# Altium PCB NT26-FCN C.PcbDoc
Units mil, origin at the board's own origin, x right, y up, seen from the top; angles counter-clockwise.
Board outline 1222.67 x 1229.6 mil, 4 copper layers (Top Layer, GND1, Signal Layer 1, Bottom Layer), stack 29.559 mil thick; 1 components, 0 nets, 46 pads, 0 vias.
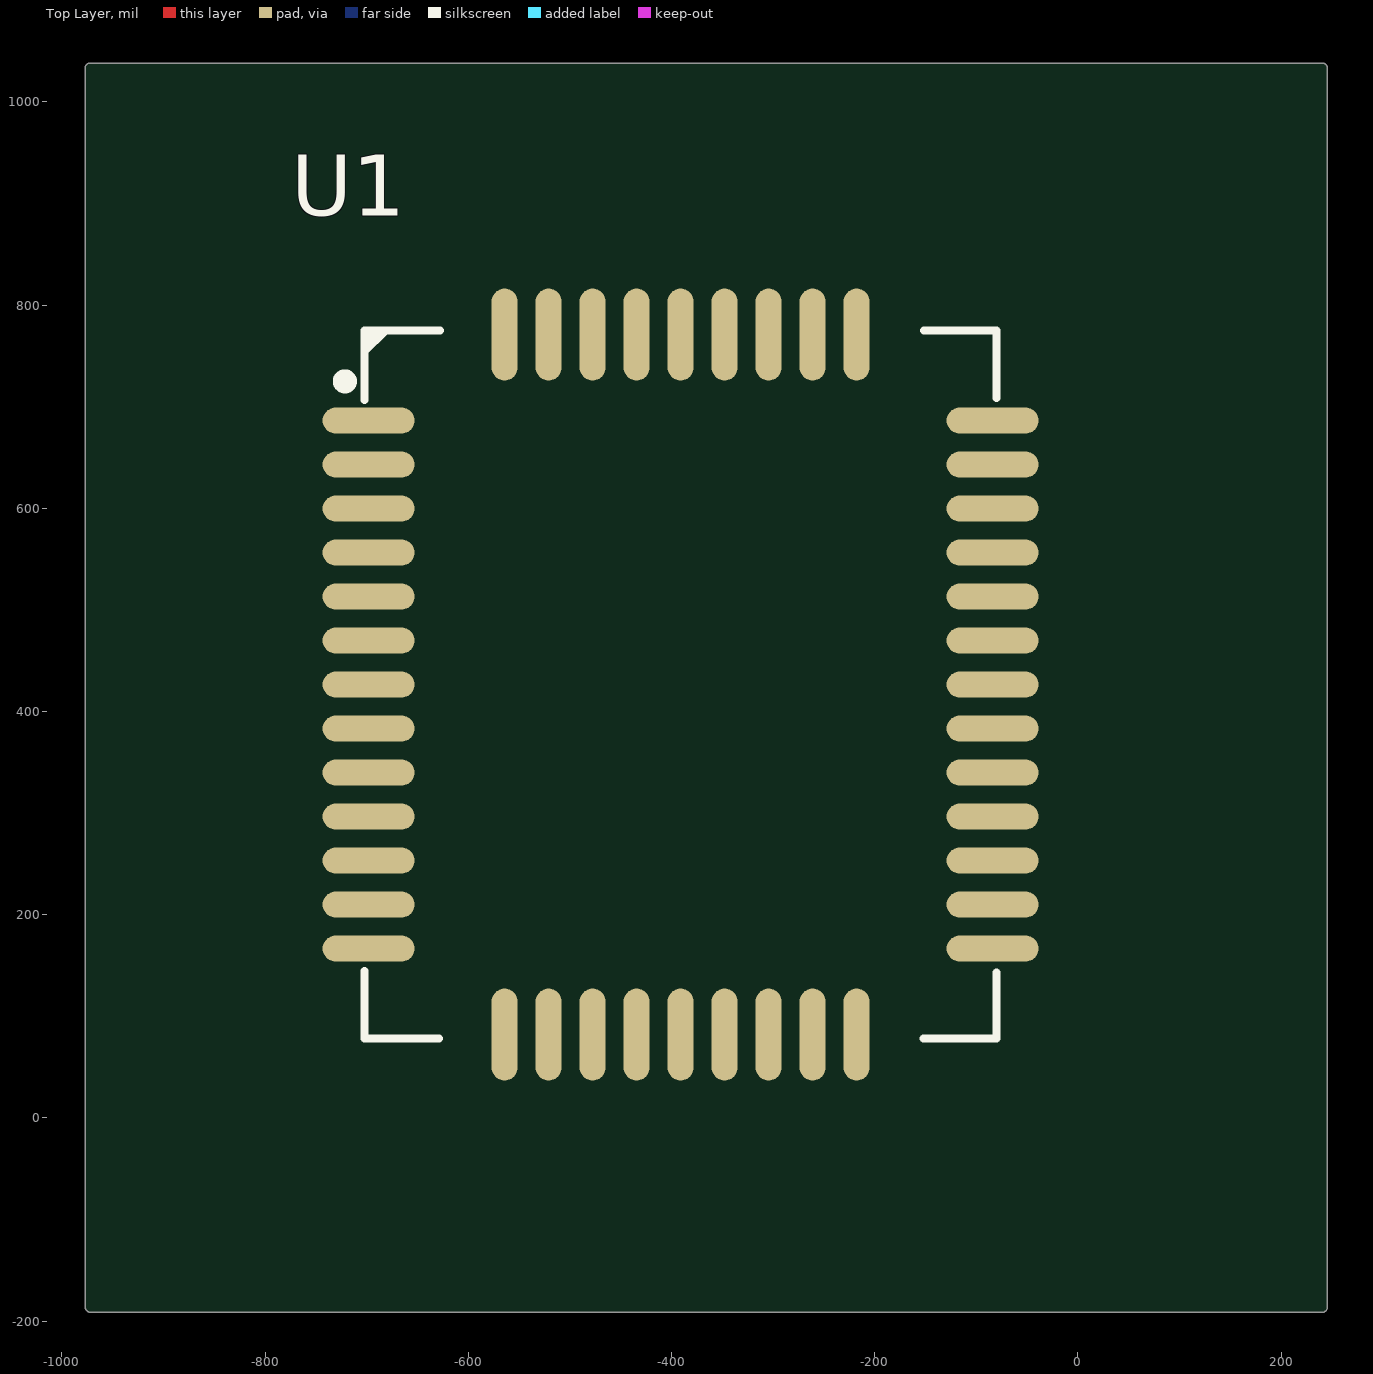
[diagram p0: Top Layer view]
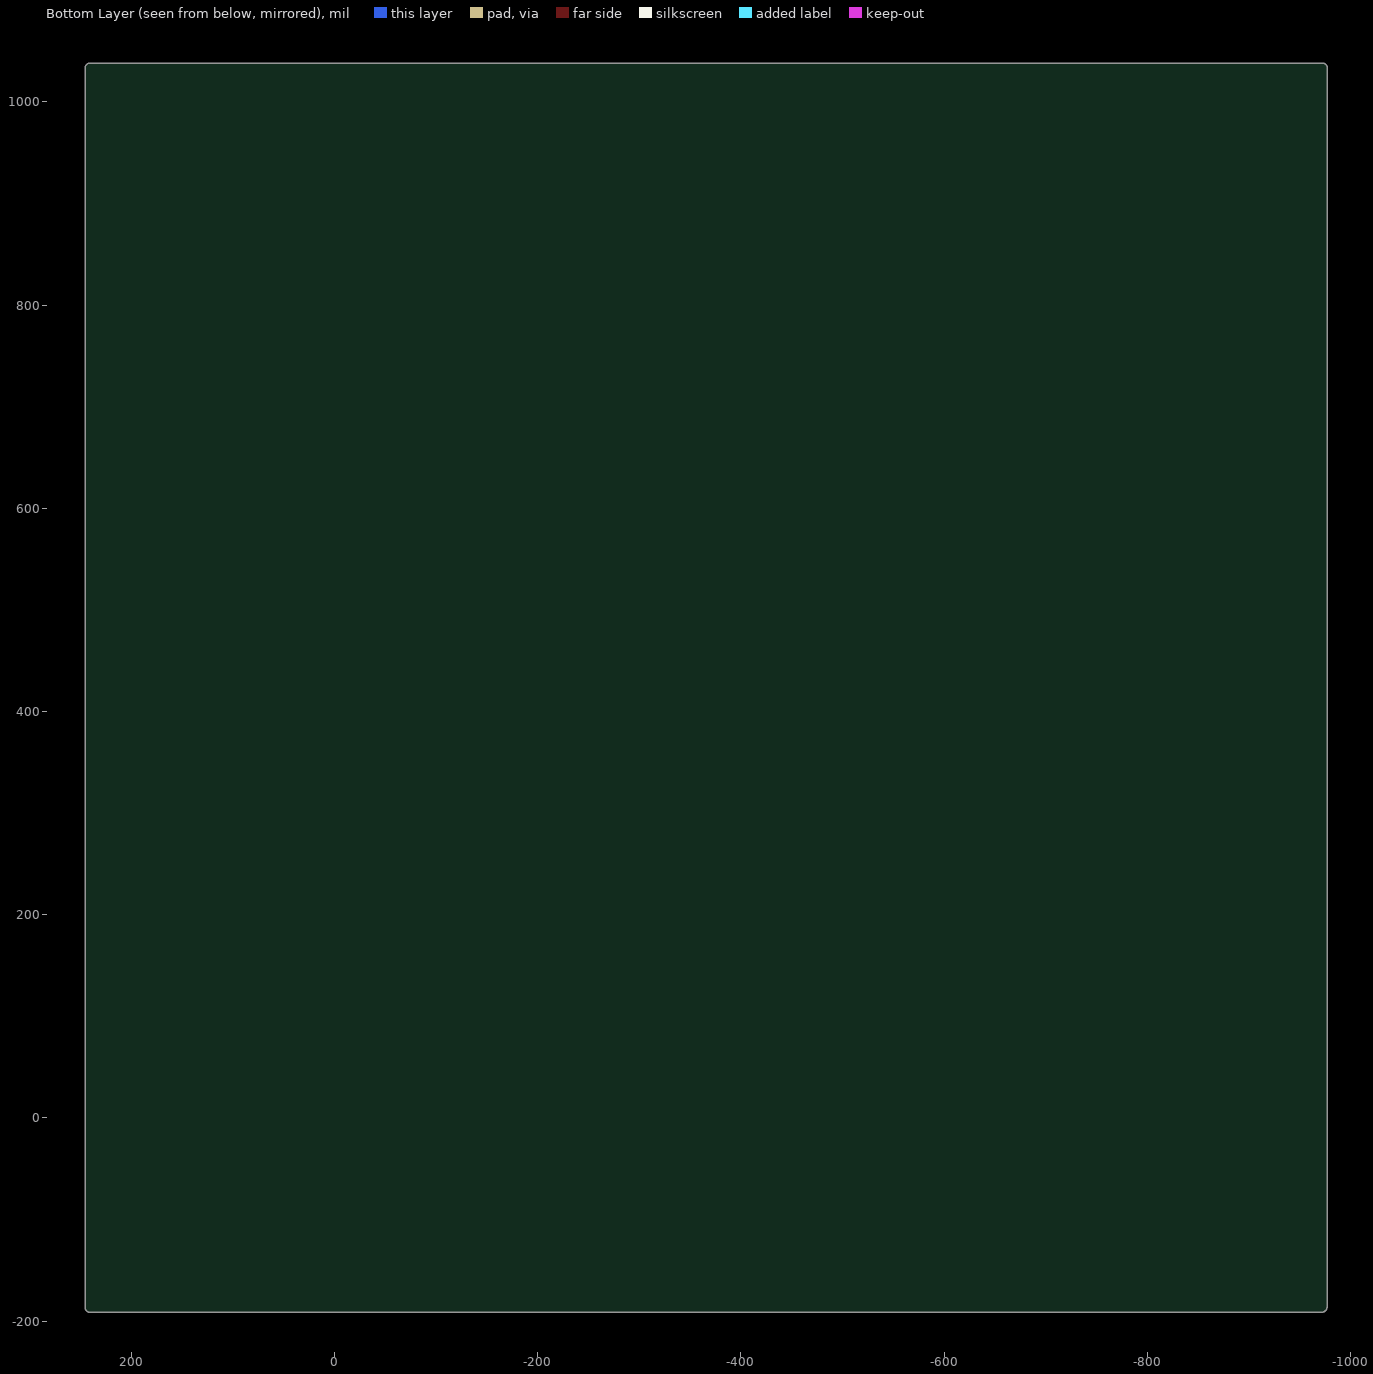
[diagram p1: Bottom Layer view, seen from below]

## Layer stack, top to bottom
Top Solder: solder mask 0.4, Solder Resist, Dk 3.5
Top Layer: signal copper 1
Dielectric1: core 2.9528, 1080, Dk 4.2
GND1: signal copper 0.9843
Dielectric2: core 19.685, 1080, Dk 4.2
Signal Layer 1: signal copper 0.9843
Dielectric 3: prepreg 2.9528, Dk 4.2
Bottom Layer: signal copper 1
Bottom Solder: solder mask 0.4, Solder Resist, Dk 3.5

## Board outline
-977.06,-185.94 -977.06,-177.78 cw(c-972.2,-176.54) -977.22,-176.54 -977.22,1033.27 cw(c-972.2,1033.27) -972.2,1038.28 240.43,1038.28 cw(c240.43,1033.27) 245.45,1033.27 245.45,-186.3 cw(c240.43,-186.3) 240.43,-191.31 -971.69,-191.31 cw(c-971.69,-186.3) -975.26,-189.83 -975.24,-189.85 -975.59,-189.49 -975.58,-189.51 cw(c-972.05,-185.94)

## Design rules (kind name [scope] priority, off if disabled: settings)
Clearance keepout [IsKeepOut] p1: gap=7.87 ignorepadtopadclearanceinfootprint=FALSE except(0: Arc-Arc Arc-Track Arc-SMDPad Arc-THPad Arc-Fill Arc-Poly Arc-Region Arc-Hole Track-Track Track-SMDPad Track-THPad Track-Fill Track-Poly Track-Region Track-Hole SMDPad-Hole THPad-Hole Via-Hole Fill-Hole Poly-Hole Region-Hole Text-Hole; 11.81: Arc-Via Track-Via)
Clearance Clearance_via [InDrillLayerPair('GND1 - Signal Layer 1') vs InDrillLayerPair('GND1 - Signal Layer 1')] p2: gap=5.91 ignorepadtopadclearanceinfootprint=TRUE
Clearance via [IsVia vs IsVia] p3: gap=5 ignorepadtopadclearanceinfootprint=FALSE except(4.2: Via-Via)
Clearance PAD&PAD [IsPad vs IsPad] p4: gap=7.87 ignorepadtopadclearanceinfootprint=TRUE
Clearance Clearance_50_TOP [InNetClass('Net Class_50') vs InNet('GND') And OnLayer('Top Layer')] p5: gap=3 ignorepadtopadclearanceinfootprint=TRUE except(0: Arc-Hole Track-Hole SMDPad-Hole THPad-Hole Via-Hole Fill-Hole Poly-Hole Region-Hole Text-Hole; 4.5: Arc-Fill Arc-Poly Arc-Region Track-Fill Track-Poly Track-Region SMDPad-Fill SMDPad-Poly SMDPad-Region THPad-Fill THPad-Poly THPad-Region Via-Fill Via-Poly Via-Region Fill-Fill Fill-Poly Fill-Region Poly-Poly Poly-Region Region-Region; 8: SMDPad-SMDPad)
Clearance Clearance_50_SIG [InNetClass('Net Class_50') vs InNet('GND') And OnLayer('Signal Layer 1')] p6: gap=3 ignorepadtopadclearanceinfootprint=TRUE except(0: Arc-Hole Track-Hole SMDPad-Hole THPad-Hole Via-Hole Fill-Hole Poly-Hole Region-Hole Text-Hole; 5: Arc-Fill Arc-Poly Arc-Region Track-Fill Track-Poly Track-Region SMDPad-Fill SMDPad-Poly SMDPad-Region THPad-Fill THPad-Poly THPad-Region Via-Fill Via-Poly Via-Region Fill-Fill Fill-Poly Fill-Region Poly-Poly Poly-Region Region-Region; 8: SMDPad-SMDPad)
Clearance Clearance_polygon [InPolygon] p7: gap=3 ignorepadtopadclearanceinfootprint=TRUE except(0: Arc-Hole Track-Hole SMDPad-Hole THPad-Hole Via-Hole Fill-Hole Poly-Hole Region-Hole Text-Hole; 5: Arc-Fill Arc-Poly Arc-Region Track-Fill Track-Poly Track-Region SMDPad-Fill SMDPad-Poly SMDPad-Region THPad-Fill THPad-Poly THPad-Region Via-Fill Via-Poly Via-Region Fill-Fill Fill-Poly Fill-Region Poly-Poly Poly-Region Region-Region; 8: SMDPad-SMDPad)
Clearance all [All] p8: gap=3 ignorepadtopadclearanceinfootprint=TRUE except(0: Arc-Hole Track-Hole SMDPad-Hole THPad-Hole Via-Hole Fill-Hole Poly-Hole Region-Hole Text-Hole; 4: Arc-Fill Arc-Poly Arc-Region Track-Fill Track-Poly Track-Region SMDPad-Fill SMDPad-Poly SMDPad-Region THPad-Fill THPad-Poly THPad-Region Via-Fill Via-Poly Via-Region Fill-Fill Fill-Poly Fill-Region Poly-Poly Poly-Region Region-Region; 8: SMDPad-SMDPad)
ComponentClearance [All] p1: gap=0 collisioncheckmode=3 verticalgap=0 showdistances=FALSE
DiffPairsRouting [All] p1: maxlimit=5 minlimit=5 mostfreqgap=5 toplayer_minwidth=3.25 toplayer_maxwidth=3.25 toplayer_prefwidth=3.25 midlayer1_minwidth=2.52 midlayer1_maxwidth=2.52 midlayer1_prefwidth=2.52 midlayer2_minwidth=2.52 midlayer2_maxwidth=2.52 midlayer2_prefwidth=2.52 bottomlayer_minwidth=3.25 bottomlayer_maxwidth=3.25 bottomlayer_prefwidth=3.25 maxuncoupledlength=500
HoleSize [All] p1: absolutevalues=TRUE maxlimit=196.85 minlimit=0 maxpercent=80.000 minpercent=20.000
HoleToHoleClearance [All] p1: gap=3 allowstackedmicrovias=TRUE
MinimumSolderMaskSliver [All] p1: minsoldermaskwidth=0
PolygonConnect [All] p1: connectstyle=Direct reliefconductorwidth=10 reliefentries=4 polygonreliefangle="90 Angle" airgapwidth=10
RoutingVias RoutingVias_1 [InDrillLayerPair('Top Layer - GND1')   OR InDrillLayerPair('Signal Layer 1 - Bottom Layer')] p1: holewidth=3.94 width=8.66 viastyle="Through Hole" minholewidth=3.94 minwidth=8.66 maxholewidth=11.81 maxwidth=19.68
RoutingVias [InDrillLayerPair('GND1 - Signal Layer 1')] p2: holewidth=7.87 width=13.78 viastyle="Through Hole" minholewidth=7.87 minwidth=13.78 maxholewidth=8.66 maxwidth=15.75
SilkToSilkClearance [All] p1: silktosilkclearance=0
SilkToSolderMaskClearance [IsPad] p1: minsilkscreentomaskgap=0 clearancetoexposedcopper=TRUE
SolderMaskExpansion [All] p1: expansion=4
Width 50 [InNetClass('Net Class_50')] p1: maxlimit=3.5 minlimit=3 preferedwidth=3.5 toplayer_minwidth=3.5 midlayer1_maxwidth=3 midlayer1_prefwidth=3 midlayer2_maxwidth=3 midlayer2_prefwidth=3 bottomlayer_minwidth=3.5 minimp=50.000000 maximp=50.000000 favimp=50.000000
Width [All] p2: maxlimit=196.85 minlimit=2.76 preferedwidth=2.99
23 further rules are at their usual default settings.

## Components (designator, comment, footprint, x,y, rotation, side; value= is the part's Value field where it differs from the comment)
U1 "NT26-FCN C" "NT26-FCN C" -391.02,426.54 r0 top

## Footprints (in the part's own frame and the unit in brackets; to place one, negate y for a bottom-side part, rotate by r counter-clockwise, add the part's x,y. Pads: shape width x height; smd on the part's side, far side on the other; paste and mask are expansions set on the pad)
"NT26-FCN C" [mm]
  round 0.8 on Mech1 mask+0.051: 0(-6.457,7.619)
  round 0.5 on Mech1: 0(0,0)
  oval 2.3x0.65 smd: 1(-7.8,6.6) 2(-7.8,5.5) 3(-7.8,4.4) 4(-7.8,3.3) 5(-7.8,2.2) 6(-7.8,1.1) 7(-7.8,0) 8(-7.8,-1.1) 9(-7.8,-2.2) 10(-7.8,-3.3) 11(-7.8,-4.4) 12(-7.8,-5.5) 13(-7.8,-6.6) 23(7.8,-6.6) 24(7.8,-5.5) 25(7.8,-4.4) 26(7.8,-3.3) 27(7.8,-2.2) 28(7.8,-1.1) 29(7.8,0) 30(7.8,1.1) 31(7.8,2.2) 32(7.8,3.3) 33(7.8,4.4) 34(7.8,5.5) 35(7.8,6.6)
  oval 0.65x2.3 smd: 14(-4.4,-8.75) 15(-3.3,-8.75) 16(-2.2,-8.75) 17(-1.1,-8.75) 18(0,-8.75) 19(1.1,-8.75) 20(2.2,-8.75) 21(3.3,-8.75) 22(4.4,-8.75) 36(4.4,8.75) 37(3.3,8.75) 38(2.2,8.75) 39(1.1,8.75) 40(0,8.75) 41(-1.1,8.75) 42(-2.2,8.75) 43(-3.3,8.75) 44(-4.4,8.75)
  silkscreen extent -8.49,-8.85 7.9,8.85

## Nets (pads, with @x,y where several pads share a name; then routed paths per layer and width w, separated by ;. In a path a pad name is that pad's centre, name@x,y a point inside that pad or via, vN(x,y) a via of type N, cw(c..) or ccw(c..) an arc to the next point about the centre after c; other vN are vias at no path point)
pads on no net: U1.0 U1.1 U1.2 U1.3 U1.4 U1.5 U1.6 U1.7 U1.8 U1.9 U1.10 U1.11 U1.12 U1.13 U1.14 U1.15 U1.16 U1.17 U1.18 U1.19 U1.20 U1.21 U1.22 U1.23 U1.24 U1.25 U1.26 U1.27 U1.28 U1.29 U1.30 U1.31 U1.32 U1.33 U1.34 U1.35 U1.36 U1.37 U1.38 U1.39 U1.40 U1.41 U1.42 U1.43 U1.44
